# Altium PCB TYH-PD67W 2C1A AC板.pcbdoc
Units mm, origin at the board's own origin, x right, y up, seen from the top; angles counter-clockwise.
Board outline 94.32 x 66.89 mm, 5 copper layers (Top Layer, Signal Layer 3, Signal Layer 1, Signal Layer 2, Bottom Layer), stack 0.941 mm thick; 7 components, 153 nets, 24 pads, 78 vias.
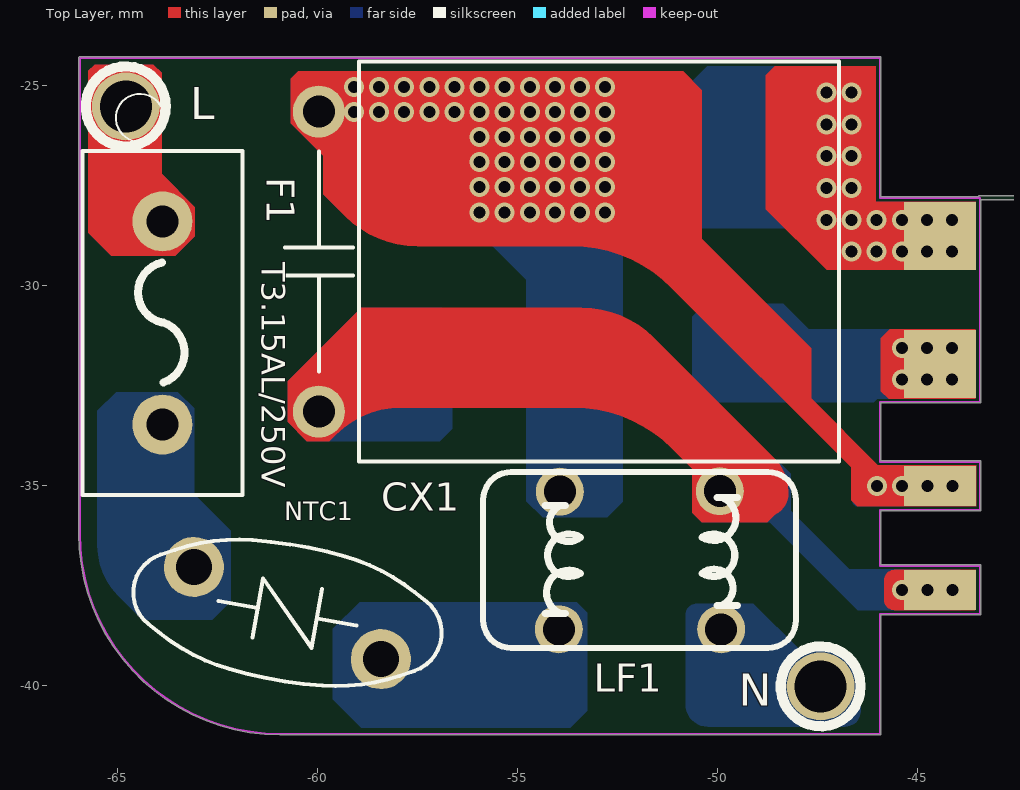
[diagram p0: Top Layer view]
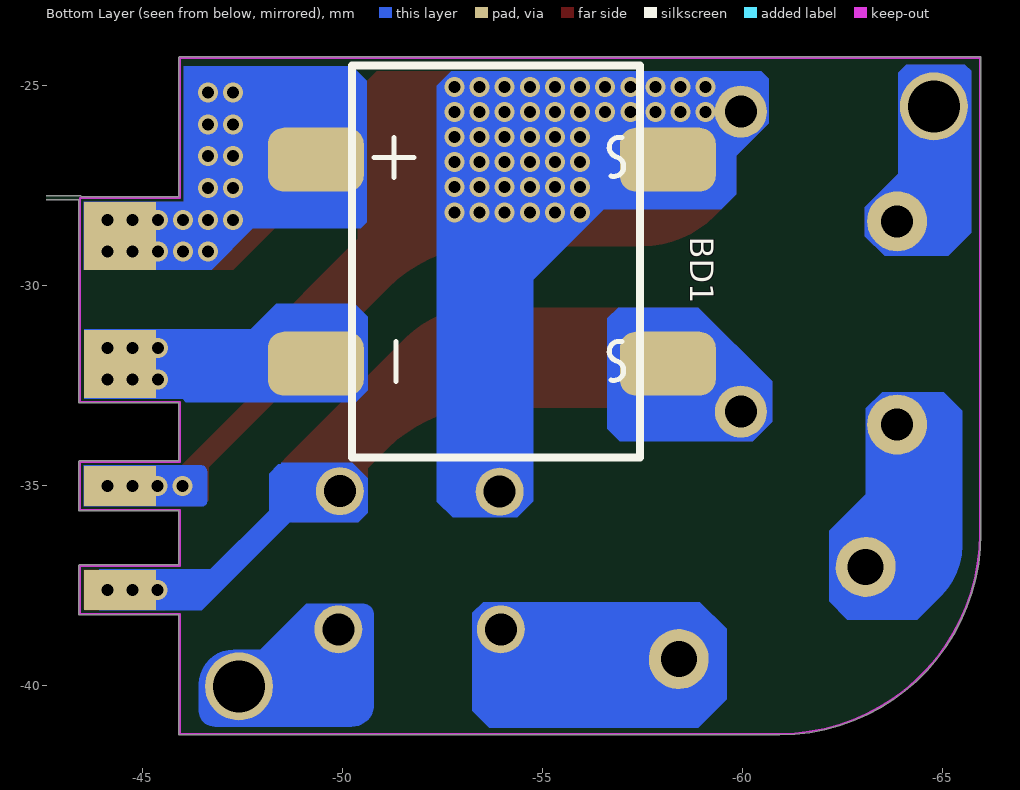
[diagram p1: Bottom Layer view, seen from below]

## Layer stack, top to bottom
Top Solder: solder mask 0.0102, Solder Resist, Dk 3.5
Top Layer: signal copper 0.0356
Dielectric 1: core 0.254, FR-4, Dk 4.2
Signal Layer 3: signal copper 0.036
Dielectric 4: prepreg 0.127, Dk 4.2
Signal Layer 1: signal copper 0.036
Dielectric 2: core 0.254, Dk 4.2
Signal Layer 2: signal copper 0.036
Dielectric 3: prepreg 0.127, Dk 4.2
Bottom Layer: signal copper 0.0356
Bottom Solder: solder mask 0.0102, Solder Resist, Dk 3.5

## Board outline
-60.945,-41.225 -45.944,-41.225 ccw(c-45.944,-41.2) -45.919,-41.2 -45.919,-38.225 -43.445,-38.225 ccw(c-43.445,-38.2) -43.419,-38.2 -43.419,-37 ccw(c-43.445,-37) -43.445,-36.975 -45.919,-36.975 -45.919,-35.625 -43.445,-35.625 ccw(c-43.445,-35.6) -43.419,-35.6 -43.419,-34.4 ccw(c-43.445,-34.4) -43.445,-34.375 -45.919,-34.375 -45.919,-32.925 -43.445,-32.925 ccw(c-43.445,-32.9) -43.419,-32.9 -43.419,-27.85 -39.751,-27.85 -39.759,-40.693 ccw(c-39.709,-40.7) -39.709,-40.75 -29.759,-40.752 -29.76,-42.002 ccw(c-29.71,-42.002) -29.71,-42.052 0,-42.052 ccw(c0,-42.002) 0.05,-42.002 0.05,-37.55 2.5,-37.55 ccw(c2.5,-37.5) 2.55,-37.5 2.55,-32.55 5.163,-32.55 5.16,-37.409 ccw(c5.21,-37.409) 5.16,-37.409 ccw(c8.207,-37.409) 8.207,-40.456 ccw(c8.207,-40.406) 8.207,-40.456 ccw(c8.207,-40.406) 8.207,-40.456 25.296,-40.456 ccw(c25.296,-40.406) 25.308,-40.455 ccw(c25.296,-37.407) 28.344,-37.407 28.352,-4.393 ccw(c28.302,-4.393) 28.352,-4.393 ccw(c28.302,-4.393) 28.351,-4.381 ccw(c25.304,-4.393) 25.304,-1.346 8.229,-1.346 ccw(c8.229,-4.393) 5.181,-4.375 ccw(c5.228,-4.393) 5.178,-4.393 5.175,-9.653 ccw(c5.225,-9.653) 5.225,-9.703 6.674,-9.704 6.673,-10.703 5.225,-10.702 ccw(c5.225,-10.753) 5.174,-10.753 5.163,-32.45 0.05,-32.45 0.05,-9.32 2.5,-9.32 ccw(c2.5,-9.269) 2.55,-9.269 2.55,-2.769 ccw(c2.5,-2.769) 2.5,-2.719 0.05,-2.719 0.05,0 ccw(c0,0) 0,0.05 -29.65,0.05 -29.65,1.682 2.433,1.682 ccw(c2.433,1.733) 2.483,1.733 ccw(c2.433,1.733) 2.482,1.745 ccw(c2.45,1.784) 2.5,1.784 2.5,3.584 ccw(c2.45,3.584) 2.45,3.635 0,3.635 0,22.484 ccw(c-0.05,22.484) -0.014,22.52 ccw(c-0.05,22.484) -0.05,22.535 -13.768,22.535 -13.768,24.784 ccw(c-13.819,24.784) -13.819,24.835 -26.819,24.835 ccw(c-26.819,24.784) -26.869,24.784 -26.869,22.535 -27.789,22.535 ccw(c-27.789,22.484) -27.84,22.483 -27.84,20.784 cw(c-28.289,20.784) -28.289,20.335 cw(c-28.289,20.784) -28.289,20.335 cw(c-28.289,20.284) -28.289,20.335 -30.217,20.335 ccw(c-30.217,20.284) -30.268,20.284 -30.268,1.733 ccw(c-30.217,1.733) -30.217,1.682 -29.75,1.682 -29.75,-1.25 -31.7,-1.25 ccw(c-31.7,-1.3) -31.75,-1.3 -31.75,-26.75 -39.7,-26.75 ccw(c-39.7,-26.8) -39.75,-26.8 -39.751,-27.75 -43.445,-27.75 ccw(c-43.445,-27.8) -43.488,-27.775 -45.919,-27.775 -45.919,-24.3 ccw(c-45.945,-24.3) -45.945,-24.275 -65.945,-24.275 ccw(c-65.945,-24.3) -65.97,-24.3 -65.97,-36.2 ccw(c-60.945,-36.2)

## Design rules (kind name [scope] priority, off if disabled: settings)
Clearance Clearance_19 [InNet('NetC4_2') vs InNet('PGND')] p1: gap=0.4
Clearance Clearance_18 [InNet('NetR15_1') vs InNet('PGND')] p2: gap=1
Clearance Clearance_17 [InNet('NetN_1') vs InNet('NetBD1_1')] p3: gap=1.55
Clearance Clearance_16 [InNet('NetN_1') vs InNet('PGND')] p4: gap=1.5
Clearance Clearance_15 [InNet('VIN') vs InNet('PGND')] p5 off: gap=5.8
Clearance Clearance_14 [InNet('CS') vs InNet('Bais-L')] p6: gap=0.45
Clearance Clearance_13 [InNet('SW') vs InNet('CS')] p7: gap=1.5
Clearance Clearance_12 [InNet('NetR15_1') vs InNet('CS')] p8: gap=1
Clearance Clearance_11 [InNet('NetBD1_3') vs InNet('CS')] p9: gap=1.1
Clearance Clearance_10 [InNet('HV') vs InNet('CS')] p10: gap=1.1
Clearance Clearance_9 [InNet('NetL2_1') vs InNet('CS')] p11: gap=1.5
Clearance Clearance_8 [InNet('NetC1_2') vs InNet('PGND')] p12: gap=1.2
Clearance Clearance_7 [InNet('NetBD1_3') vs InNet('PGND')] p13: gap=1.2
Clearance Clearance_6 [InNet('NetC2_2') vs InNet('PGND')] p14: gap=1.3
Clearance Clearance_5 [InNet('Bais-L') vs InNet('PGND')] p15: gap=0.45
Clearance Clearance_4 [InNet('SW') vs InNet('PGND')] p16: gap=1.5
Clearance Clearance_3 [InNet('HV') vs InNet('PGND')] p17: gap=1.2
Clearance Clearance_2 [InNet('NetL2_1') vs InNet('PGND')] p18: gap=1.5
Clearance Clearance_1 [OnLayer('Keep-Out Layer')] p19: gap=0.1
Clearance [All] p20: gap=0.2
PlaneConnect [All] p1: planeconnectstyle=Direct reliefexpansion=0.508 reliefentries=4 reliefconductorwidth=0.3 reliefairgap=0.254
PolygonConnect [All] p1: connectstyle=Direct reliefconductorwidth=0.3 reliefentries=4 polygonreliefangle="90 Angle" airgapwidth=0.3
RoutingVias [All] p1: holewidth=0.711 width=1.27 viastyle="Through Hole" minholewidth=0.711 minwidth=1.27 maxholewidth=0.711 maxwidth=1.27
SolderMaskExpansion [All] p1: expansion=0.05
Width [All] p1: maxlimit=10 minlimit=0.1 preferedwidth=0.2
28 further rules are at their usual default settings.

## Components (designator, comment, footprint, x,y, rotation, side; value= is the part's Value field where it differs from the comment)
BD1 "WRMSB40M" BD-WRLSB80M -49.344,-26.848 r180 bottom
CX1 "0.1uF" X-0.22SW -59.97,-33.147 r90 top
F1 "T3.15AL/250V" FUSE-5mm-l -63.878,-28.388 r270 top
L "Comment" PAD-AC -64.796,-25.515 r90 top
LF1 "Comment" L-6*3*3 -48.24,-36.854 r270 top
N "Comment" PAD-AC -47.423,-40.013 r90 top
NTC1 "" 5D-7-2 -61.365,-38.051 r160 top (schematic designator NTC)

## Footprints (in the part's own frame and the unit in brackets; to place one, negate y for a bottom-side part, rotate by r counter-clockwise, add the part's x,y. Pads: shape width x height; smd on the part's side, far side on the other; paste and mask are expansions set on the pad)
5D-7-2 [mm]
  round 1.5 hole 0.9: 1(1.973,-0.371) 2(-3.207,0.197)
  silkscreen extent -4.47,-1.92 3.24,1.74, body extent -5.36,-2.63 4.13,2.46, height 9.5
BD-WRLSB80M [mm]
  rrect50% 2.4x1.6 smd: 1(0,0) 2(8.8,0) 3(8.8,-5.1) 4(0,-5.1)
  silkscreen extent 0.9,-7.45 8.1,2.35, body extent -0.61,-7.55 9.39,2.45, height 1.61
FUSE-5mm-l [mm]
  round 1.5 hole 0.8: 1(0,0) 2(5.08,0)
  silkscreen extent -1.76,-2 6.84,2, body extent -1.76,-2 6.84,2, height 5.2
L-6*3*3 [mm]
  round 1.2 hole 0.8: 1(1.733,-5.729) 2(1.734,-1.669) 3(-1.708,-5.703) 4(-1.72,-1.706)
  silkscreen extent -2.2,-7.62 2.2,0.2, body extent -1.95,-7.4 2,0.02, height 7.21
PAD-AC [mm]
  round 1.7 hole 1.3: 1(0,0)
  silkscreen extent -1,-1 1,1
X-0.22SW [mm]
  round 1.3 hole 0.8: 1(0,0) 2(7.5,0)
  silkscreen extent -1.25,-13 8.75,0.85, body extent -1.25,-13 8.75,0.2, height 5.2

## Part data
BD1: library part BRIDGE1
CX1: library part Cap_dip, "Capacitor"
F1: library part FUSE2
NTC1: library part NTC

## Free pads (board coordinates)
  rect 1.8x1 smd far side: 0(-44.445,-37.6) 0(-44.445,-35)
  rect 1.8x1 smd: 0(-44.445,-37.6) 0(-44.445,-35)
  rect 1.8x1.7 smd far side: 0(-44.445,-31.95) 0(-44.445,-28.75)
  rect 1.8x1.7 smd: 0(-44.445,-31.95) 0(-44.445,-28.75)

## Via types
v1: diameter 0.5, hole 0.3, Top Layer to Bottom Layer, tented both sides, 78 vias

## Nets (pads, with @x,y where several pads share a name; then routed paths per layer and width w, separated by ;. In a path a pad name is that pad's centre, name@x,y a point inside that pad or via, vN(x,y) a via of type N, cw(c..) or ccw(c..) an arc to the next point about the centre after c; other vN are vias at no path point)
3.3V: 
A: 
A+: 
A-: 
Bais-L: 
BOOT0: 
CC1: 
CC2: 
CPA: 
CS: 
D: NTC1.2
D+: 
D-: 
DM: 
DP: 
EM: 
EN: 
EN_IC: 
FB: 
G-SR: 
GND-C: 
HV: 
ISET: 
KEY: 
KEY1: 
LEDA: 
M: 
N: LF1.2 N.1
NetBD1_1: BD1.2 CX1.2 LF1.3 pad.0@-44.445,-35 | length 23.7
  Top Layer w0.2: -53.626,-28.366 -52.48,-28.366 ; -52.475,-28.507 -46.76,-34.222 ccw(c-44.964,-32.426) pad.0@-44.964,-34.966
  Bottom Layer w0.2: BD1.2@-58.149,-26.707 -56.337,-26.707 cw(c-56.337,-29.247) -54.541,-27.451 -53.626,-28.366 ; -53.622,-28.507 cw(c-55.418,-30.303) -52.878,-30.303 -52.878,-35.132 ; v1@-45.349,-35 pad.0@-44.817,-35
  other v1: -46.014,-35 -45.386,-35 -44.758,-35 -44.131,-35 -55.951,-28.163 -55.323,-28.163 -54.695,-28.163 -54.068,-28.163 -53.44,-28.163 -52.812,-28.163 -55.951,-27.535 -55.323,-27.535 -54.695,-27.535 -54.068,-27.535 -53.44,-27.535 -52.812,-27.535 -55.951,-26.907 -55.323,-26.907 -54.695,-26.907 -54.068,-26.907 -53.44,-26.907 -52.812,-26.907 -55.951,-26.279 -55.323,-26.279 -54.695,-26.279 -54.068,-26.279 -53.44,-26.279 -52.812,-26.279 -59.09,-25.651 -58.463,-25.651 -57.835,-25.651 -57.207,-25.651 -56.579,-25.651 -55.951,-25.651 -55.323,-25.651 -54.695,-25.651 -54.068,-25.651 -53.44,-25.651 -52.812,-25.651 -59.09,-25.024 -58.463,-25.024 -57.835,-25.024 -57.207,-25.024 -56.579,-25.024 -55.951,-25.024 -55.323,-25.024 -54.695,-25.024 -54.068,-25.024 -53.44,-25.024 -52.812,-25.024
NetBD1_3: BD1.1 pad.0@-44.445,-28.75 | length 5.3
  Bottom Layer w0.2: BD1.1 -48.261,-26.848 -46.36,-28.75 pad.0@-44.817,-28.75
  other v1: -46.65,-29.148 -46.022,-29.148 -45.395,-29.148 -44.767,-29.148 -44.139,-29.148 -47.278,-28.352 -46.65,-28.352 -46.022,-28.352 -45.395,-28.352 -44.767,-28.352 -44.139,-28.352 -47.278,-27.556 -46.65,-27.556 -47.278,-26.759 -46.65,-26.759 -47.278,-25.963 -46.65,-25.963 -47.278,-25.167 -46.65,-25.167
NetBD2_1: 
NetC1_2: 
NetC2_2: 
NetC3_2: 
NetC4_1: 
NetC4_2: 
NetC6_1: 
NetC10_2: 
NetC21_1: 
NetC22_1: 
NetC24_1: 
NetC25_2: 
NetC26_2: 
NetC30_2: 
NetC31_2: 
NetC100_2: 
NetC101_1: 
NetC101_2: 
NetC112_1: 
NetD4_K: 
NetF1_1: F1.1 L.1
NetF1_2: F1.2 NTC1.1
NetKEY1_1: 
NetL2_1: 
NetLF1_2: LF1.1
NetN_1: BD1.3 CX1.1 LF1.4 pad.0@-44.445,-37.6 | length 17.6
  Top Layer w0.2: CX1.1 -59.535,-32.712 cw(c-57.739,-34.508) -57.739,-31.968 -53.085,-31.968 cw(c-53.085,-34.508) -51.289,-32.712 -48.881,-35.12
  Bottom Layer w0.2: -48.881,-35.12 -47.145,-36.856 ccw(c-45.349,-35.06) -45.349,-37.6 pad.0@-44.817,-37.6
  other v1: -45.386,-37.6 -44.758,-37.6 -44.131,-37.6
NetNTC2_1: 
NetQ1_3: 
NetQ3_4: 
NetR15_1: 
NetR25_2: 
NetR29_1: 
NetR31_2: 
NetR32_2: 
NetR41_2: 
NetR42_2: 
NetR134_1: 
NetRX1_2: 
NetRX3_2: 
NetU1_26: 
NetU1_27: 
NetU1_28: 
NetU1_29: 
NetU1_30: 
NetU1_32: 
NewNet1: 
NewNet2: 
NewNet3: 
NewNet4: 
NewNet5: 
NewNet6: 
NewNet7: 
NewNet8: 
NewNet9: 
NewNet10: 
NewNet11: 
NewNet12: 
NewNet13: 
NewNet14: 
NewNet15: 
NewNet16: 
NewNet18: 
NewNet22: 
NewNet23: 
NewNet24: 
NewNet25: 
NewNet28: 
NewNet32: 
NewNet33: 
NewNet34: 
NewNet36: 
NewNet38: 
NewNet40: 
NewNet41: 
NewNet42: 
OPTO: 
OTP: 
PA2: 
PA4: 
PA5: 
PA6: 
PA7: 
PA8: 
PA9: 
PB0: 
PB1: 
PF0: 
PF1: 
PF3: 
PGND: BD1.4 pad.0@-44.445,-31.95 | length 4.5
  Bottom Layer w0.3: BD1.4@-49.343,-31.95 pad.0@-44.817,-31.95
  other v1: -45.395,-32.348 -44.767,-32.348 -44.139,-32.348 -45.395,-31.552 -44.767,-31.552 -44.139,-31.552
RS: 
RST: 
SCL: 
SCL1: 
SDA: 
SDA1: 
SET: 
SGND: 
SRCG_A: 
SW: 
SW-SR: 
SWCLK: 
SWCLK1: 
SWCLK2: 
SWDIO: 
SWDIO1: 
SWDIO2: 
SWRST: 
TXD: 
U2-2: 
V3V3: 
VBUS: 
VC: 
VDD: 
VDD1: 
VDS: 
VFB: 
VFB1: 
VIN: 
VMS: 
VOUT1: 
VXO: 
XGND: 

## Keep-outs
Keep-Out Layer:
  lines w0.05: -65.945,-36.2 ccw(c-60.945,-36.2) -60.945,-41.2 -45.944,-41.2 -45.944,-38.2 -43.445,-38.2 -43.445,-37 -45.944,-37 -45.944,-35.6 -43.445,-35.6 -43.445,-34.4 -45.944,-34.4 -45.944,-32.9 -43.445,-32.9 -43.445,-27.8 -45.945,-27.8 -45.945,-24.3 -65.945,-24.3 -65.945,-36.2

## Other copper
Top Layer:
  region net NetN_1: -48.266,-35.415 -48.76,-35.91 -50.402,-35.91 -50.638,-35.674 -50.638,-33.942 -50.553,-33.857 -49.503,-33.857 -48.241,-35.119 -48.241,-35.293
  region net NetF1_1: -65.732,-24.629 -65.732,-28.677 -65.16,-29.249 -63.562,-29.249 -63.071,-28.758 -63.071,-28.032 -63.902,-27.202 -63.902,-24.672 -64.106,-24.467 -65.57,-24.467
  region net NetBD1_3: -43.544,-29.603 -47.276,-29.603 -48.799,-28.08 -48.799,-24.741 -48.567,-24.509 -46.049,-24.509 -46.049,-27.899 -43.544,-27.899
  region net PGND: -43.553,-32.826 -45.727,-32.826 -45.919,-32.634 -45.919,-31.315 -45.692,-31.087 -43.553,-31.087
  region net NetN_1: -45.835,-37.643 -45.835,-37.36 cw(c-45.578,-37.36) -45.578,-37.104 -43.549,-37.104 -43.549,-38.077 cw(c-43.577,-38.077) -43.577,-38.105 -45.581,-38.105 cw(c-45.581,-37.853) -45.833,-37.853
  region net NetBD1_1: -60.485,-24.639 -50.862,-24.639 -50.397,-25.105 -50.397,-28.829 -47.662,-31.564 -47.662,-32.815 -45.991,-34.487 -43.538,-34.487 -43.538,-35.511 -46.507,-35.511 -46.662,-35.356 -46.662,-34.536 -51.153,-30.045 ccw(c-53.661,-32.553) -53.661,-29.006 -57.511,-29.006 cw(c-57.511,-26.466) -59.307,-28.262 -59.853,-27.716 -59.853,-26.754 -60.673,-25.935 -60.673,-24.826
  region net NetN_1: -59.704,-33.883 -59.546,-33.725 cw(c-57.898,-35.373) -57.898,-33.043 -53.602,-33.043 cw(c-53.602,-36.512) -51.149,-34.059 -49.778,-35.429 ccw(c-48.891,-34.542) -48.891,-35.797 -48.855,-35.797 ccw(c-48.855,-35.171) -48.229,-35.171 ccw(c-49.449,-35.171) -48.587,-34.309 -51.605,-31.29 ccw(c-53.401,-33.087) -53.401,-30.547 -58.911,-30.547 -60.752,-32.388 -60.752,-33.4 -60.269,-33.883
Bottom Layer:
  region net NetN_1: -48.481,-34.429 -50.259,-34.429 -50.638,-34.808 -50.638,-35.674 -50.402,-35.91 -48.726,-35.91 -48.481,-35.665
  region: -56.159,-37.908 -58.948,-37.908 -59.619,-38.579 -59.619,-40.339 -58.909,-41.049 -56.318,-41.049 -55.88,-40.612 -55.88,-38.186
  region net PGND: -43.553,-31.087 -47.721,-31.087 -48.357,-30.451 -50.313,-30.451 -50.639,-30.777 -50.639,-32.614 -50.345,-32.908 -46.097,-32.908 -46.014,-32.826 -43.553,-32.826
  region net NetBD1_3: -50.623,-24.873 -50.623,-28.409 -50.465,-28.567 -47.773,-28.567 -46.737,-29.603 -43.544,-29.603 -43.544,-27.899 -46.049,-27.899 -46.049,-24.509 -50.26,-24.509
  region net NetN_1: -49.391,-34.459 -48.411,-34.459 -48.176,-34.695 -48.176,-35.621 -46.709,-37.087 -43.934,-37.087 -43.934,-38.11 -46.496,-38.11 -48.696,-35.91 -49.296,-35.91 -49.613,-35.593 -49.613,-34.681
  region net NetBD1_1: -52.726,-24.639 -52.367,-24.998 -52.367,-35.395 -52.763,-35.791 -54.375,-35.791 -54.783,-35.383 -54.783,-29.852 -56.548,-28.087 -59.482,-28.087 -59.853,-27.716 -59.853,-26.754 -60.673,-25.935 -60.673,-24.826 -60.485,-24.639
  region net NetLF1_2: -57.846,-41.049 -53.683,-41.049 -53.259,-40.625 -53.259,-38.173 -53.524,-37.908 -56.159,-37.908 -58.154,-39.902 -58.154,-40.741
  region net NetN_1: -60.269,-33.883 -56.943,-33.883 -56.633,-33.572 -56.633,-30.815 -56.901,-30.547 -58.911,-30.547 -60.752,-32.388 -60.752,-33.4
  region net NetF1_1: -65.732,-24.629 -65.732,-28.677 -65.16,-29.249 -63.562,-29.249 -63.071,-28.758 -63.071,-28.032 -63.902,-27.202 -63.902,-24.672 -64.106,-24.467 -65.57,-24.467
  region net N: -49.104,-37.943 -47.949,-39.097 -47.285,-39.097 cw(c-47.285,-39.958) -46.423,-39.958 -46.423,-40.632 cw(c-46.813,-40.632) -46.813,-41.021 -50.245,-41.021 cw(c-50.245,-40.467) -50.799,-40.467 -50.799,-38.23 cw(c-50.512,-38.23) -50.512,-37.943
  region net NetF1_2: -65.04,-32.655 -63.501,-32.655 -63.089,-33.066 -63.089,-35.215 -62.175,-36.129 -62.175,-37.888 -62.633,-38.345 -64.38,-38.345 -64.994,-37.731 cw(c-63.763,-36.5) -65.504,-36.5 -65.504,-33.119
  region net NetBD1_1: -46.507,-35.511 -43.538,-35.511 -43.538,-34.487 -46.474,-34.487 ccw(c-46.474,-34.637) -46.625,-34.637 -46.625,-35.394 ccw(c-46.507,-35.394)

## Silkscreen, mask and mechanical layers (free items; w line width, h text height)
Top Overlay:
  circle w0.05: c-64.445,-25.8 r0.6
